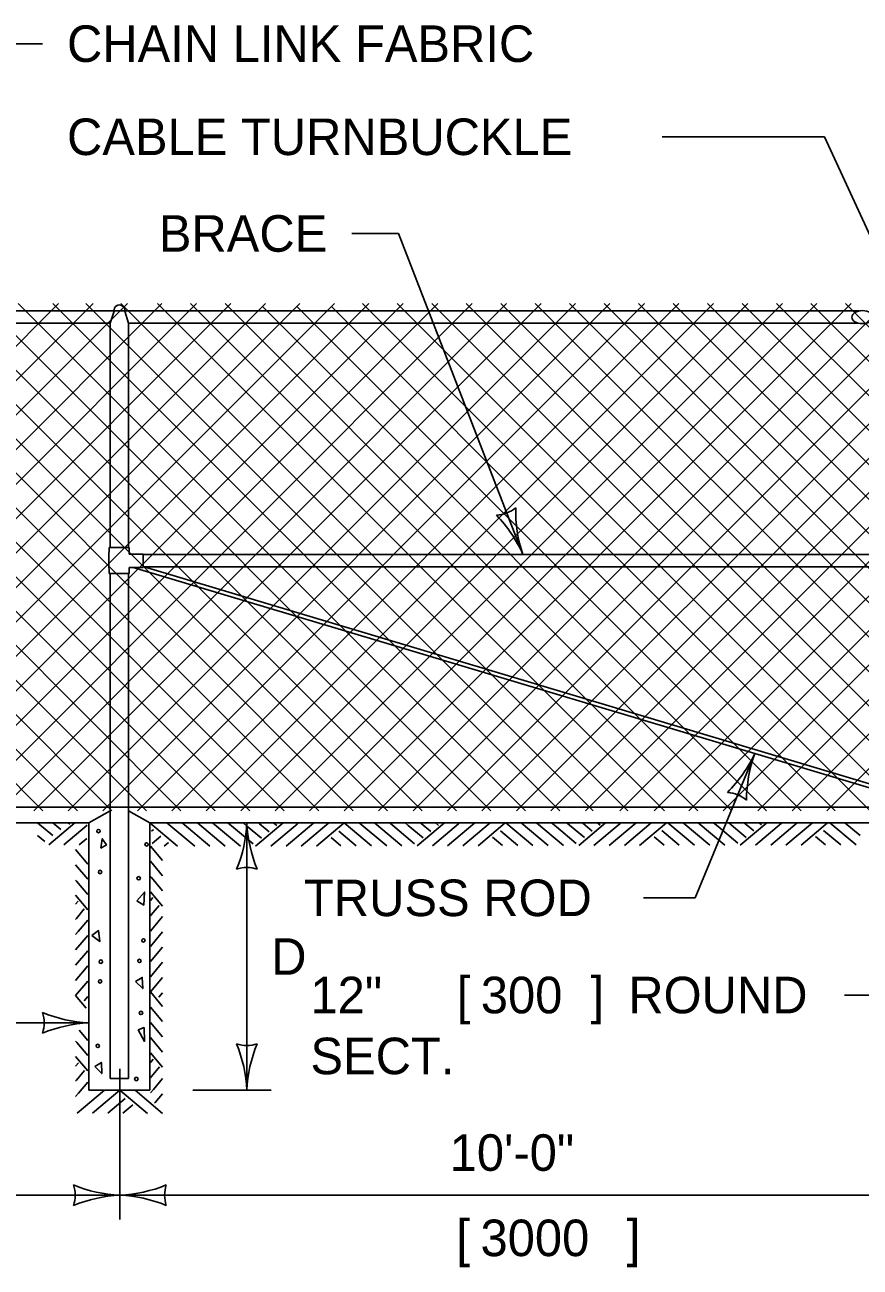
# Model space of a CAD drawing. Extents: x 49973.1 to 50021, y 49987.6 to 50015.4.
# Drawn here: x 49975.97 to 49977.341, y 50013.224 to 50015.263 of the extents above; entities that cross this region are included whole.
import ezdxf

# ---------------------------------------------------------------- set-up
doc = ezdxf.new("R2010")
doc.units = 0
for name, color, linetype in [('Level 1', 7, 'Continuous'), ('Level 2', 7, 'Continuous'), ('Level 3', 7, 'Continuous')]:
    doc.layers.add(name, color=color, linetype=linetype)

msp = doc.modelspace()

# ---------------------------------------------------------------- linework, layer by layer
at = {"layer": 'Level 1'}
for p, q in [((49974.4702, 50014.7932), (49977.3392, 50014.7932)), ((49975.1672, 50014.8053), (49975.9998, 50013.9729)), ((49975.1931, 50013.9729), (49976.0255, 50014.8053)), ((49975.2235, 50014.8053), (49976.0564, 50013.9729)), ((49975.2497, 50013.9729), (49976.0821, 50014.8053)), ((49975.2804, 50014.8053), (49976.113, 50013.9729)), ((49975.3061, 50013.9729), (49976.1385, 50014.8053)), ((49975.337, 50014.8053), (49976.1696, 50013.9729)), ((49975.3627, 50013.9729), (49976.1951, 50014.8053)), ((49975.3935, 50014.8053), (49976.2262, 50013.9729)), ((49975.4193, 50013.9729), (49976.2517, 50014.8053)), ((49975.45, 50014.8053), (49976.2826, 50013.9729)), ((49975.4759, 50013.9729), (49976.3083, 50014.8053)), ((49975.5068, 50014.8053), (49976.3392, 50013.9729)), ((49975.5325, 50013.9729), (49976.3649, 50014.8053)), ((49975.5633, 50014.8053), (49976.3958, 50013.9729)), ((49975.5891, 50013.9729), (49976.4215, 50014.8053)), ((49975.6199, 50014.8053), (49976.4524, 50013.9729)), ((49975.6457, 50013.9729), (49976.4781, 50014.8053)), ((49975.6765, 50014.8053), (49976.509, 50013.9729)), ((49975.7021, 50013.9729), (49976.5345, 50014.8053)), ((49975.7331, 50014.8053), (49976.5656, 50013.9729)), ((49975.7587, 50013.9729), (49976.5911, 50014.8053)), ((49975.7895, 50014.8053), (49976.622, 50013.9729)), ((49975.8153, 50013.9729), (49976.6477, 50014.8053)), ((49975.8461, 50014.8053), (49976.6786, 50013.9729)), ((49975.8719, 50013.9729), (49976.7043, 50014.8053)), ((49975.9027, 50014.8053), (49976.7352, 50013.9729)), ((49975.9285, 50013.9729), (49976.7609, 50014.8053)), ((49975.9593, 50014.8053), (49976.7918, 50013.9729)), ((49975.9851, 50013.9729), (49976.8175, 50014.8053)), ((49976.0159, 50014.8053), (49976.8484, 50013.9729)), ((49976.0415, 50013.9729), (49976.8739, 50014.8053)), ((49976.0705, 50014.8053), (49976.9028, 50013.9729)), ((49976.0982, 50013.973), (49976.9305, 50014.8053)), ((49976.1102, 50014.7732), (49976.1165, 50014.7927)), ((49976.1279, 50014.8053), (49976.9599, 50013.9729)), ((49976.1402, 50014.7732), (49976.1342, 50014.793)), ((49976.1548, 50013.973), (49976.9871, 50014.8053)), ((49976.1879, 50014.8053), (49977.02, 50013.9729)), ((49976.2113, 50013.9729), (49977.0437, 50014.8053)), ((49976.2421, 50014.8053), (49977.0744, 50013.9729)), ((49976.2679, 50013.9729), (49977.1003, 50014.8053)), ((49976.2987, 50014.8053), (49977.1305, 50013.9729)), ((49976.3245, 50013.9729), (49977.1569, 50014.8053)), ((49976.3601, 50014.8005), (49977.1875, 50013.9729)), ((49976.3811, 50013.9729), (49977.2135, 50014.8053)), ((49976.4167, 50014.8005), (49977.2441, 50013.9729)), ((49976.4375, 50013.9729), (49977.2699, 50014.8053)), ((49976.4733, 50014.8005), (49977.3003, 50013.9729)), ((49976.4941, 50013.9729), (49977.3265, 50014.8053)), ((49976.5244, 50014.8053), (49977.3574, 50013.9729)), ((49976.5507, 50013.9729), (49977.3831, 50014.8053)), ((49976.5812, 50014.8053), (49977.4139, 50013.9729)), ((49976.6073, 50013.9729), (49977.4397, 50014.8053)), ((49976.6379, 50014.8053), (49977.4706, 50013.9729)), ((49976.6637, 50013.9729), (49977.4872, 50014.7964)), ((49976.6946, 50014.8053), (49977.4851, 50014.015)), ((49976.7511, 50014.8053), (49977.4849, 50014.0718)), ((49976.8077, 50014.8053), (49977.4849, 50014.1283)), ((49976.8642, 50014.8053), (49977.4853, 50014.1843)), ((49976.921, 50014.8053), (49977.4854, 50014.2409)), ((49976.9774, 50014.8053), (49977.4851, 50014.2977)), ((49977.0341, 50014.8053), (49977.4848, 50014.3547)), ((49977.0907, 50014.8053), (49977.4793, 50014.4168)), ((49977.1473, 50014.8053), (49977.485, 50014.4676)), ((49977.2039, 50014.8053), (49977.4848, 50014.5244)), ((49977.2603, 50014.8053), (49977.4854, 50014.5802)), ((49977.3169, 50014.8053), (49977.4858, 50014.6365)), ((49974.7402, 50014.7732), (49976.1102, 50014.7732)), ((49976.1102, 50014.7732), (49976.1102, 50014.405)), ((49976.1402, 50014.7732), (49976.1402, 50014.405)), ((49976.1402, 50014.7732), (49977.3383, 50014.7732)), ((49976.7203, 50013.9729), (49977.4842, 50014.7368)), ((49976.7769, 50013.9729), (49977.4839, 50014.6799)), ((49976.8335, 50013.9729), (49977.4802, 50014.6196)), ((49976.8901, 50013.9729), (49977.4848, 50014.5676)), ((49976.9468, 50013.973), (49977.4843, 50014.5105)), ((49977.0032, 50013.973), (49977.4852, 50014.455)), ((49976.1086, 50014.405), (49976.1414, 50014.405)), ((49976.1414, 50014.405), (49976.1414, 50014.3942)), ((49976.1414, 50014.3942), (49976.1646, 50014.3942)), ((49976.1646, 50014.3721), (49976.1646, 50014.3942)), ((49976.1646, 50014.3932), (49977.4781, 50014.3932)), ((49977.0598, 50013.973), (49977.4842, 50014.3974)), ((49976.1416, 50014.3624), (49976.1416, 50014.3721)), ((49976.1416, 50014.3721), (49976.1646, 50014.3721)), ((49977.4761, 50013.9747), (49976.1482, 50014.3721)), ((49976.1646, 50014.3732), (49977.4781, 50014.3732)), ((49977.4761, 50013.9811), (49976.1658, 50014.3732)), ((49976.1086, 50014.3624), (49976.1416, 50014.3624)), ((49976.1102, 50014.3624), (49976.1102, 50013.973)), ((49976.1402, 50014.3624), (49976.1402, 50013.973)), ((49977.1164, 50013.973), (49977.4855, 50014.3421)), ((49977.173, 50013.973), (49977.4845, 50014.2845)), ((49977.2296, 50013.973), (49977.4842, 50014.2276)), ((49977.2862, 50013.973), (49977.4843, 50014.1711)), ((49974.4705, 50013.9786), (49977.4631, 50013.9786)), ((49976.0752, 50013.9532), (49976.1102, 50013.9729)), ((49976.1102, 50013.973), (49976.1102, 50013.5332)), ((49976.1402, 50013.973), (49976.1402, 50013.5332)), ((49976.1752, 50013.9531), (49976.1402, 50013.9726)), ((49974.7752, 50013.9532), (49976.0752, 50013.9532)), ((49975.9945, 50013.9504), (49975.9912, 50013.9531)), ((49976.0159, 50013.9325), (49975.9945, 50013.9504)), ((49976.0093, 50013.917), (49976.0522, 50013.9531)), ((49976.0293, 50013.9422), (49976.0162, 50013.9531)), ((49976.0343, 50013.917), (49976.0727, 50013.9492)), ((49976.0438, 50013.9509), (49976.0412, 50013.9531)), ((49976.0729, 50013.9532), (49976.0752, 50013.9532)), ((49976.0752, 50013.9532), (49976.0752, 50013.5141)), ((49976.1752, 50013.5141), (49976.1752, 50013.9531)), ((49976.2207, 50013.915), (49976.1752, 50013.9531)), ((49976.1752, 50013.9531), (49977.4652, 50013.9531)), ((49976.1778, 50013.9392), (49976.1813, 50013.9421)), ((49976.2489, 50013.9149), (49976.2034, 50013.953)), ((49976.2739, 50013.9149), (49976.2285, 50013.953)), ((49976.2989, 50013.9149), (49976.2534, 50013.953)), ((49976.3239, 50013.9149), (49976.2784, 50013.953)), ((49976.3125, 50013.9454), (49976.3033, 50013.953)), ((49976.3448, 50013.9183), (49976.3125, 50013.9454)), ((49976.3341, 50013.9483), (49976.3284, 50013.953)), ((49976.3587, 50013.9277), (49976.3341, 50013.9483)), ((49976.3489, 50013.9149), (49976.3942, 50013.953)), ((49976.3555, 50013.9513), (49976.3534, 50013.953)), ((49976.3712, 50013.9382), (49976.3555, 50013.9513)), ((49976.3739, 50013.9149), (49976.4169, 50013.951)), ((49976.3789, 50013.9526), (49976.3784, 50013.953)), ((49976.3839, 50013.9484), (49976.3789, 50013.9526)), ((49976.3989, 50013.9149), (49976.4442, 50013.953)), ((49976.4169, 50013.951), (49976.4192, 50013.953)), ((49976.4239, 50013.9149), (49976.4692, 50013.953)), ((49976.4489, 50013.9149), (49976.4942, 50013.953)), ((49976.514, 50013.9154), (49976.4856, 50013.9392)), ((49976.539, 50013.9154), (49976.4942, 50013.953)), ((49976.564, 50013.9154), (49976.519, 50013.953)), ((49976.589, 50013.9154), (49976.544, 50013.953)), ((49976.5776, 50013.9459), (49976.569, 50013.953)), ((49976.6099, 50013.9188), (49976.5776, 50013.9459)), ((49976.5992, 50013.9488), (49976.5941, 50013.953)), ((49976.6238, 50013.9282), (49976.5992, 50013.9488)), ((49976.614, 50013.9154), (49976.6587, 50013.953)), ((49976.6206, 50013.9518), (49976.6191, 50013.953)), ((49976.6363, 50013.9387), (49976.6206, 50013.9518)), ((49976.639, 50013.9154), (49976.682, 50013.9515)), ((49976.649, 50013.9489), (49976.644, 50013.9531)), ((49976.664, 50013.9154), (49976.7087, 50013.953)), ((49976.682, 50013.9515), (49976.6837, 50013.953)), ((49976.689, 50013.9154), (49976.7337, 50013.953)), ((49976.714, 50013.9154), (49976.7587, 50013.953)), ((49976.7791, 50013.9159), (49976.7507, 50013.9397)), ((49976.8041, 50013.9159), (49976.7598, 50013.953)), ((49976.8291, 50013.9159), (49976.7847, 50013.953)), ((49976.8541, 50013.9159), (49976.8097, 50013.953)), ((49976.8427, 50013.9464), (49976.8347, 50013.953)), ((49976.875, 50013.9193), (49976.8427, 50013.9464)), ((49976.8643, 50013.9493), (49976.8598, 50013.953)), ((49976.8889, 50013.9287), (49976.8643, 50013.9493)), ((49976.8791, 50013.9159), (49976.9232, 50013.953)), ((49976.8857, 50013.9523), (49976.8848, 50013.953)), ((49976.9014, 50013.9392), (49976.8857, 50013.9523)), ((49976.9041, 50013.9159), (49976.9471, 50013.952)), ((49976.9141, 50013.9494), (49976.9098, 50013.953)), ((49976.9291, 50013.9159), (49976.9732, 50013.953)), ((49976.9471, 50013.952), (49976.9482, 50013.953)), ((49976.9541, 50013.9159), (49976.9982, 50013.953)), ((49976.9791, 50013.9159), (49977.0232, 50013.953)), ((49977.0442, 50013.9164), (49977.0158, 50013.9402)), ((49977.0692, 50013.9164), (49977.0255, 50013.953)), ((49977.0942, 50013.9164), (49977.0504, 50013.953)), ((49977.1192, 50013.9164), (49977.0754, 50013.953)), ((49977.1078, 50013.9469), (49977.1004, 50013.953)), ((49977.1401, 50013.9198), (49977.1078, 50013.9469)), ((49977.1294, 50013.9498), (49977.1255, 50013.953)), ((49977.154, 50013.9292), (49977.1294, 50013.9498)), ((49977.1442, 50013.9164), (49977.1877, 50013.953)), ((49977.1508, 50013.9528), (49977.1505, 50013.953)), ((49977.1665, 50013.9397), (49977.1508, 50013.9528)), ((49977.1692, 50013.9164), (49977.2122, 50013.9525)), ((49977.1792, 50013.9499), (49977.1755, 50013.953)), ((49977.1942, 50013.9164), (49977.2377, 50013.953)), ((49977.2122, 50013.9525), (49977.2127, 50013.953)), ((49977.2192, 50013.9164), (49977.2627, 50013.953)), ((49977.2442, 50013.9164), (49977.2877, 50013.953)), ((49977.3093, 50013.9169), (49977.2809, 50013.9407)), ((49977.3343, 50013.9169), (49977.2912, 50013.953)), ((49977.3343, 50013.9169), (49977.2912, 50013.953)), ((49977.3409, 50013.9322), (49977.3161, 50013.953)), ((49976.0028, 50013.9224), (49975.9911, 50013.9323)), ((49976.0593, 50013.917), (49976.0717, 50013.9274)), ((49976.179, 50013.9192), (49976.1934, 50013.9312)), ((49976.1989, 50013.9149), (49976.2057, 50013.9206)), ((49976.489, 50013.9154), (49976.4727, 50013.9291)), ((49976.7541, 50013.9159), (49976.7378, 50013.9296)), ((49977.0192, 50013.9164), (49977.0029, 50013.9301)), ((49977.2843, 50013.9169), (49977.268, 50013.9306)), ((49976.0734, 50013.8854), (49976.0535, 50013.9091)), ((49976.1963, 50013.8913), (49976.1764, 50013.915)), ((49976.0734, 50013.8604), (49976.0535, 50013.8841)), ((49976.1963, 50013.8663), (49976.1764, 50013.89)), ((49976.055, 50013.8574), (49976.0535, 50013.8591)), ((49976.0734, 50013.8354), (49976.055, 50013.8574)), ((49976.1779, 50013.8633), (49976.1764, 50013.865)), ((49976.1963, 50013.8413), (49976.1779, 50013.8633)), ((49976.0734, 50013.8104), (49976.0535, 50013.8341)), ((49976.1963, 50013.8163), (49976.1764, 50013.84)), ((49976.0576, 50013.8244), (49976.0534, 50013.8194)), ((49976.1805, 50013.8303), (49976.1763, 50013.8253)), ((49976.1907, 50013.8176), (49976.1776, 50013.8019)), ((49976.0547, 50013.796), (49976.0535, 50013.7945)), ((49976.0678, 50013.8117), (49976.0547, 50013.796)), ((49976.0734, 50013.7933), (49976.0577, 50013.7746)), ((49976.1776, 50013.8019), (49976.1764, 50013.8004)), ((49976.1963, 50013.7992), (49976.1806, 50013.7805)), ((49976.0577, 50013.7746), (49976.0535, 50013.7695)), ((49976.1806, 50013.7805), (49976.1764, 50013.7754)), ((49976.1963, 50013.7741), (49976.1835, 50013.7589)), ((49976.0606, 50013.753), (49976.0535, 50013.7444)), ((49976.0734, 50013.7682), (49976.0606, 50013.753)), ((49976.1835, 50013.7589), (49976.1764, 50013.7503)), ((49976.0734, 50013.7432), (49976.0535, 50013.7194)), ((49976.1963, 50013.7491), (49976.1764, 50013.7253)), ((49976.0734, 50013.7182), (49976.0535, 50013.6944)), ((49976.1963, 50013.7241), (49976.1764, 50013.7003)), ((49976.0734, 50013.6933), (49976.0535, 50013.6696)), ((49976.1963, 50013.6992), (49976.1764, 50013.6755)), ((49976.1963, 50013.6518), (49976.1764, 50013.6755)), ((49976.1963, 50013.6741), (49976.1902, 50013.6669)), ((49976.0708, 50013.649), (49976.0535, 50013.6696)), ((49976.0734, 50013.6682), (49976.0673, 50013.661)), ((49976.1963, 50013.6268), (49976.1764, 50013.6505)), ((49976.0734, 50013.5959), (49976.0595, 50013.6125)), ((49976.1963, 50013.6018), (49976.1764, 50013.6255)), ((49976.0555, 50013.5923), (49976.0535, 50013.5946)), ((49976.0734, 50013.5709), (49976.0555, 50013.5923)), ((49976.1784, 50013.5982), (49976.1764, 50013.6005)), ((49976.1963, 50013.5768), (49976.1784, 50013.5982)), ((49976.0734, 50013.5459), (49976.0535, 50013.5696)), ((49976.1963, 50013.5518), (49976.1764, 50013.5755)), ((49976.0539, 50013.5543), (49976.0535, 50013.5538)), ((49976.0581, 50013.5593), (49976.0539, 50013.5543)), ((49976.1768, 50013.5602), (49976.1764, 50013.5597)), ((49976.181, 50013.5652), (49976.1768, 50013.5602)), ((49976.1912, 50013.5525), (49976.1781, 50013.5368)), ((49976.0552, 50013.5309), (49976.0535, 50013.5288)), ((49976.0683, 50013.5466), (49976.0552, 50013.5309)), ((49976.1102, 50013.5332), (49976.1402, 50013.5332)), ((49976.1781, 50013.5368), (49976.1764, 50013.5347)), ((49976.1963, 50013.5335), (49976.1811, 50013.5154)), ((49976.0582, 50013.5095), (49976.0535, 50013.5038)), ((49976.0562, 50013.4766), (49976.1011, 50013.5141)), ((49976.0734, 50013.5276), (49976.0582, 50013.5095)), ((49976.0752, 50013.5141), (49976.1752, 50013.5141)), ((49976.0812, 50013.4766), (49976.1259, 50013.5141)), ((49976.1713, 50013.4761), (49976.1262, 50013.5141)), ((49976.1963, 50013.4761), (49976.1512, 50013.5141)), ((49976.1811, 50013.5154), (49976.1764, 50013.5097)), ((49976.1963, 50013.5084), (49976.184, 50013.4938)), ((49976.1062, 50013.4766), (49976.1346, 50013.5004)), ((49976.1312, 50013.4766), (49976.1475, 50013.4903)), ((49976.184, 50013.4938), (49976.1832, 50013.4928))]:
    msp.add_line(p, q, dxfattribs=at)
for points in [[(49976.0951, 50013.9112), (49976.0972, 50013.9269), (49976.104, 50013.9167)], [(49976.1542, 50013.8249), (49976.1666, 50013.8393), (49976.1652, 50013.8181)], [(49976.0802, 50013.7681), (49976.0912, 50013.7763), (49976.0933, 50013.7584)], [(49976.1519, 50013.6925), (49976.1629, 50013.6994), (49976.1636, 50013.6809)], [(49976.1564, 50013.6135), (49976.166, 50013.617), (49976.1667, 50013.5943)], [(49976.0848, 50013.553), (49976.0958, 50013.5599), (49976.0965, 50013.5414)]]:
    msp.add_lwpolyline(points, close=True, dxfattribs=at)
for centre in [(49976.0911, 50013.9395), (49976.1699, 50013.9176), (49976.0936, 50013.8723), (49976.157, 50013.862), (49976.1647, 50013.76), (49976.0949, 50013.7251), (49976.1582, 50013.7264), (49976.0936, 50013.6928), (49976.1608, 50013.6411), (49976.0898, 50013.5868), (49976.1531, 50013.5326)]:
    msp.add_circle(centre, 0.00279, dxfattribs=at)
for centre, radius, start, end in [((49976.1254, 50014.7942), 0.00895, 352.3754, 189.572), ((49976.3599, 50014.3837), 0.2521, 175.1522, 184.845)]:
    msp.add_arc(centre, radius, start, end, dxfattribs=at)
msp.add_ellipse((49977.3449, 50014.7831), major_axis=(-0.0175, 0.0001), ratio=0.610393, dxfattribs=at)
at = {"layer": 'Level 3'}
for p, q in [((49975.9173, 50015.2319), (49975.9994, 50015.2319)), ((49977.2826, 50015.0791), (49977.0163, 50015.0791)), ((49977.4156, 50014.7897), (49977.2826, 50015.0791)), ((49976.5833, 50014.9204), (49976.5069, 50014.9204)), ((49976.7876, 50014.3932), (49976.5833, 50014.9204)), ((49977.168, 50014.0669), (49977.0704, 50013.8299)), ((49976.3345, 50013.5141), (49976.3345, 50013.9531)), ((49977.0704, 50013.8299), (49976.9855, 50013.8299)), ((49977.3155, 50013.6704), (49977.4652, 50013.6704)), ((49975.8744, 50013.6247), (49976.0752, 50013.6247)), ((49976.1261, 50013.5492), (49976.1261, 50013.3018)), ((49976.3745, 50013.5141), (49976.2459, 50013.5141)), ((49974.7252, 50013.3418), (49976.1261, 50013.3418)), ((49976.1261, 50013.3418), (49977.5299, 50013.3418))]:
    msp.add_line(p, q, dxfattribs=at)
for centre, radius, start, end in [((49976.7412, 50014.5127), 0.0548, 273.3757, 309.0981), ((49976.998, 50014.4652), 0.2223, 178.6929, 198.8764), ((49976.5749, 50014.2982), 0.233, 24.0642, 43.3141), ((49976.9662, 50014.1602), 0.2223, 315.0054, 335.1889), ((49977.3875, 50013.9887), 0.233, 160.3767, 179.6266), ((49977.1191, 50013.9484), 0.0548, 49.6882, 85.4106), ((49976.1124, 50013.9623), 0.2223, 337.456, 357.6395), ((49976.5673, 50013.9646), 0.233, 182.8273, 202.0772), ((49976.3345, 50013.8249), 0.0548, 72.1388, 107.8612), ((49976.0844, 50013.8469), 0.2223, 247.456, 267.6395), ((49975.947, 50013.6247), 0.0548, 342.1388, 17.8612), ((49976.0867, 50013.392), 0.233, 92.8273, 112.0772), ((49976.3345, 50013.6423), 0.0548, 252.1388, 287.8612), ((49976.1018, 50013.5026), 0.233, 2.8273, 22.0772), ((49976.5567, 50013.505), 0.2223, 157.456, 177.6395), ((49976.1353, 50013.564), 0.2223, 247.456, 267.6395), ((49975.9979, 50013.3418), 0.0548, 342.1388, 17.8612), ((49976.1147, 50013.5745), 0.233, 272.8273, 292.0772), ((49976.2544, 50013.3418), 0.0548, 162.1388, 197.8612), ((49976.1376, 50013.1091), 0.233, 92.8273, 112.0772), ((49976.117, 50013.1197), 0.2223, 67.456, 87.6395)]:
    msp.add_arc(centre, radius, start, end, dxfattribs=at)

# ---------------------------------------------------------------- texts
at = {"layer": 'Level 2'}
for s, p in [('CHAIN LINK FABRIC', (49976.0394, 50015.2019)), ('CABLE TURNBUCKLE', (49976.0394, 50015.0491)), ('BRACE', (49976.1901, 50014.8904)), ('TRUSS ROD', (49976.4282, 50013.7999)), ('D', (49976.3745, 50013.7036)), ('12" ', (49976.4389, 50013.6404)), ('[', (49976.6789, 50013.6404)), ('300', (49976.7185, 50013.6404)), (']', (49976.8985, 50013.6404)), (' ROUND', (49976.9382, 50013.6404)), ('SECT.', (49976.4389, 50013.5404)), ('10\'-0"', (49976.6674, 50013.3818)), ('[', (49976.6783, 50013.2418)), (']', (49976.958, 50013.2418)), ('3000', (49976.718, 50013.2418))]:
    msp.add_text(s, height=0.06, dxfattribs=at).set_placement(p)

doc.saveas('drawing.dxf')
